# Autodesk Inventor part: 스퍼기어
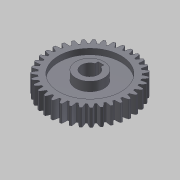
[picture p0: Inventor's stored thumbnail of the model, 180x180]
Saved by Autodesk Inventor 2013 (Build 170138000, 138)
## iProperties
Created: 2013-08
Part Number: 스퍼기어
Material: 강
Document SubType Name: Modeling
Designer: 한국산업디자인학원
Categories: <?xml version="1.0" encoding="UTF-16"?> <MemberInstance><Categories><FamilyTemplate><FamilyTemplateParameter ValueType="xs:double" Id="1" ObjectReferenceKey="da
Density: 1 g/cm^3
CustomPartVersion: 1
Author: 한국산업디자인학원
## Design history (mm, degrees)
sketch "Sketch1"
  geometry: C1 r 37 at (0, 0)
  constraints: 1 centre point
  dimensions: "d0" = 74 diameter of C1 (= da_da)
extrude "Extrusion1" new body sketch "Sketch1" distance "d1" = 15 (= da_b); taper "d2" = 0 deg
workplane "Work Plane2"
feature "피치 지름" dims "d4" = 10, "d5" = 0
workplane "Work Plane8"
workplane "Work Plane9"
feature "스퍼 기어" dims "da_b" = 15, "da_d" = 70, "da_aw" = 70, "da_da" = 74, "da_df" = 65, "da_dw" = 70, angle "da_beta" = 0 deg, "da_lefttooth" = 0, "da_righttooth" = 0
sketch "스케치3"
  geometry: L1 (-0.05, 18)-(12.45, 18); L2 (12.45, 18)-(12.45, -13); L3 (12.45, -13)-(-0.05, -13); L4 (31.515, 0)-(36.248, 0) reference; L5 (36.248, 0)-(36.544, 0) reference; L6 (36.544, 0)-(32.296, 0) reference; L7 (32.296, 0)-(32.426, 0) reference; L8 (32.426, 0)-(36.991, 0) reference; L9 (36.991, 0)-(36.991, 0) reference; L10 (36.991, 0)-(32.426, 0) reference; L11 (32.426, 0)-(32.296, 0) reference; L12 (32.296, 0)-(36.544, 0) reference; L13 (36.544, 0)-(36.248, 0) reference; L14 (36.248, 0)-(31.515, 0) reference; L15 (31.515, 0)-(31.127, 0) reference; L16 (31.127, 0)-(34.924, 0) reference; L17 (34.924, 0)-(34.34, 0) reference; L18 (34.34, 0)-(29.591, 0) reference; L19 (29.591, 0)-(28.958, 0) reference; L20 (28.958, 0)-(32.18, 0) reference; L21 (32.18, 0)-(31.329, 0) reference; L22 (31.329, 0)-(26.715, 0) reference; L23 (26.715, 0)-(25.858, 0) reference; L24 (25.858, 0)-(28.403, 0) reference; L25 (28.403, 0)-(27.31, 0) reference; L26 (27.31, 0)-(22.981, 0) reference; L27 (22.981, 0)-(21.927, 0) reference; L28 (21.927, 0)-(23.712, 0) reference; L29 (23.712, 0)-(22.414, 0) reference; L30 (22.414, 0)-(18.508, 0) reference; L31 (18.508, 0)-(17.291, 0) reference; L32 (17.291, 0)-(18.26, 0) reference; L33 (18.26, 0)-(16.798, 0) reference; L34 (16.798, 0)-(13.441, 0) reference; L35 (13.441, 0)-(12.1, 0) reference; L36 (12.1, 0)-(12.22, 0) reference; L37 (12.22, 0)-(10.641, 0) reference; L38 (10.641, 0)-(7.941, 0) reference; L39 (7.941, 0)-(6.519, 0) reference; L40 (6.519, 0)-(5.788, 0) reference; L41 (5.788, 0)-(4.143, 0) reference; L42 (4.143, 0)-(2.186, 0) reference; L43 (2.186, 0)-(0.729, 0) reference; L44 (0.729, 0)-(-0.83, 0) reference; L45 (-0.83, 0)-(-2.489, 0) reference; L46 (-2.489, 0)-(-3.639, 0) reference; L47 (-3.639, 0)-(-5.084, 0) reference; L48 (-5.084, 0)-(-7.422, 0) reference; L49 (-7.422, 0)-(-9.041, 0) reference; L50 (-9.041, 0)-(-9.347, 0) reference; L51 (-9.347, 0)-(-10.734, 0) reference; L52 (-10.734, 0)-(-13.775, 0) reference; L53 (-13.775, 0)-(-15.302, 0) reference; L54 (-15.302, 0)-(-14.755, 0) reference; L55 (-14.755, 0)-(-16.039, 0) reference; L56 (-16.039, 0)-(-19.685, 0) reference; L57 (-19.685, 0)-(-21.071, 0) reference; L58 (-21.071, 0)-(-19.688, 0) reference; L59 (-19.688, 0)-(-20.828, 0) reference; L60 (-20.828, 0)-(-24.963, 0) reference; L61 (-24.963, 0)-(-26.163, 0) reference; L62 (-26.163, 0)-(-23.989, 0) reference; L63 (-23.989, 0)-(-24.948, 0) reference; L64 (-24.948, 0)-(-29.438, 0) reference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; 2 further points
  constraints: 10 end point, 2 equal length, 2 perpendicular, 1 horizontal, 1 midpoint, 1 vertical alignment
  dimensions: "d52" = 31 distance between parallel lines of L1 L3; "d54" = 3 distance from line of L1 L170.end; "d55" = 25 diameter of L2 L284
revolve "회전1" sketch "스케치3" stored, may be unused: angle "d56" = 90 deg
sketch "스케치4"
  geometry: L1 (-12.55, 18)-(12.45, 18) reference; L2 (12.45, 0)-(-12.55, 0) reference; L3 (-12.55, -13)-(12.45, -13) reference; L4 (-0.05, 18)-(-0.05, -13); L5 (-0.05, 18)-(-7.55, 18); L6 (-7.55, -13)-(-0.05, -13); L7 (-7.55, -13)-(-7.55, 18); L8 (-0.05, 18)-(-0.05, -13); L9 (-27.55, 5)-(-12.55, 5); L10 (-12.55, 5)-(-12.55, 0); L11 (-12.55, 0)-(-27.55, 0); L12 (-27.55, 0)-(-27.55, 5); L13 (-27.55, 15)-(-12.55, 15); L14 (-12.55, 15)-(-12.55, 10); L15 (-12.55, 10)-(-27.55, 10); L16 (-27.55, 10)-(-27.55, 15); 5 further points
  constraints: 26 end point, 5 midpoint, 4 collinear, 4 parallel, 3 perpendicular, 2 horizontal, 2 horizontal alignment, 2 point on line
  dimensions: "d57" = 15 diameter of L7 L4; "d64" = 25 diameter of L10 L4; "d65" = 55 diameter of L12 L4; "d66" = 5 distance of L11.end L9.start; "d67" = 5 distance between parallel lines of L13 L15
revolve "회전2" sketch "스케치4" stored, may be unused: angle "d58" = 90 deg
sketch "스케치7"
  geometry: L1 (-2.5, 9.8)-(2.5, 9.8); L2 (2.5, 9.8)-(2.5, 0); L3 (2.5, 0)-(-2.5, 0); L4 (-2.5, 0)-(-2.5, 9.8); C1 r 7.5 at (0, 0) reference; 2 further points
  constraints: 8 end point, 2 parallel, 1 coincident, 1 horizontal, 1 midpoint, 1 perpendicular
  dimensions: "d68" = 9.8 distance from line of C1.centre L1; "d69" = 5 distance of L1.start L1.end
extrude "돌출3" cut sketch "스케치7" stored distance "d70" = 10; taper "d71" = 0 deg
body "Solid1"
sketch "Sketch2"
  geometry: C1 r 37 at (0, 0) reference; C2 r 35 at (0, 0)
  constraints: 1 centre point, 1 coincident
  dimensions: "d3" = 70 diameter of C2 (= da_dw)
body "Srf1"
node "투영된 루프1"
node "투영된 루프2"
other parameters: "d17" = 0, "d34" = 0.8976 (computed from da_z), "d39" = 0, "d41" = 0, "d47" = 0, "d48" = 0
